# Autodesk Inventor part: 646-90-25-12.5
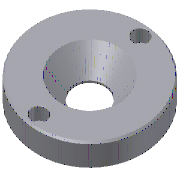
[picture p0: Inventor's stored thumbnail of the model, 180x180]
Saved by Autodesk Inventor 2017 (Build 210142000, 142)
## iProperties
Created: 2016-02
Part Number: 646-90-25-12.5
Material: ANFOR XC 38 TS
Description: Locating Ring
Document SubType Name: Modeling
Designer: Sandeep
Standard Revision: 1
Manufacturer: RABOURDIN
Language: en-US
Size Designation: 646-90-25-12.5
Categories: <MemberInstance><Categories><Category DisplayName="Mold" InternalName="349578f2-f4d4-4954-8c09-8e99297a61c0" Mnemonic="MOLD"><Category DisplayName="Locatings" I
Density: 7.845 g/cm^3
Appearance: Default
IsCustomPart: 1
Author: Sandeep
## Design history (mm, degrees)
sketch "Sketch1"
  geometry: L1 (0, -2.5)-(0, 15) reference; L2 (24, 12.5)-(12.5, 1); L3 (12.5, 1)-(12.5, 0); L4 (12.5, 0)-(45, 0); L5 (45, 0)-(45, 12.5); L6 (45, 12.5)-(24, 12.5); 1 further point
  constraints: 10 end point, 2 horizontal, 2 vertical, 1 point on line
  dimensions: "d0" = 45 deg angle of L1 L2; "d1" = 25 diameter of L3 L1 (= D2); "d2" = 90 diameter of L5 L1 (= D1); "d3" = 12.5 distance between parallel lines of L4 L6 (= A_); "d4" = 1 distance from line of L2.end L4 (= C_)
revolve "Revolution1" sketch "Sketch1" stored, may be unused: angle "d5" = 90 deg
sketch "Sketch2"
  geometry: 3 further points
  constraints: 2 vertical alignment
  dimensions: "d29" = 37 distance of point (0, 0) point (0, 37); "d30" = 37 distance of point (0, -37) point (0, 0)
hole "Hole1" sketch "Sketch2" diameter "d7" = 7; stored, may be unused: countersink angle "d11" = 90 deg, drill point angle "d13" = 0 deg; dims "d8" = 6, "d9" = 11, "d10" = 7, "d12" = 12.5 (= A_)
hole "Hole2" sketch "Sketch2" diameter "d31" = 7; stored, may be unused: countersink angle "d35" = 90 deg, drill point angle "d37" = 0 deg; dims "d32" = 6, "d33" = 11, "d34" = 7, "d36" = 12.5 (= A_)
chamfer "Chamfer1" distance "d14" = 1; stored, may be unused: second distance "d15" = 2, angle "d16" = 45 deg
chamfer "Chamfer2" distance "d17" = 0.5; stored, may be unused: second distance "d18" = 2, angle "d19" = 45 deg
chamfer "Chamfer3" distance "d20" = 0.3; stored, may be unused: second distance "d21" = 2, angle "d22" = 45 deg
sketch "Sketch3"
  geometry: L1 (0, -2.5)-(0, 15) reference; L2 (0, 0)-(45, 0); L3 (45, 0)-(45, 12.5); L4 (45, 12.5)-(0, 12.5); L5 (0, 12.5)-(0, 0)
  constraints: 8 end point, 2 parallel, 1 horizontal, 1 perpendicular
  dimensions: "d23" = 90 diameter of L3 L1 (= D1_CS); "d24" = 12.5 distance between parallel lines of L2 L4 (= A_CS)
feature "RevolutionSrf1" sketch "Sketch3" dims angle "d25" = 90 deg
body "Solid1"
body "Srf1"
other parameters: "D1" = 90 [user parameter; used in 1 equation term], "D2" = 25 [user parameter; used in 1 equation term], "A_" = 12.5 [user parameter; used in 3 equation terms], "C_" = 1 [user parameter; used in 1 equation term], "D1_CS" = 90 [user parameter; used in 1 equation term], "A_CS" = 12.5 [user parameter; used in 1 equation term], "d26" = 0, "d27" = 0, "d28" = 0
